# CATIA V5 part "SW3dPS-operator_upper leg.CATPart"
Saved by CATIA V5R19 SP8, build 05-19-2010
Part number: SW3dPS-operator_upper leg
Revision: ANY
Definition: SW3dPS-operator_upper leg
Source: Unknown
Bounding box of the stored display mesh (mm): x -80.01 to 80.01, y -514.163 to 80.01, z -80.01 to 80.01
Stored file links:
  G:\EU_thinkMotion\CFAO_2010\MMS_groupe1\MMS_groupe1\OK\rragonneau\rragonneau\SW3dPS-operator_upper leg.CATPart
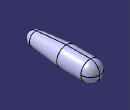
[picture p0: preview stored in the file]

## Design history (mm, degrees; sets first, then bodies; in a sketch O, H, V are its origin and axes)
Body1 "NONE" (main body)
  Solid1 "Manifold Solid #11031": solid without history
